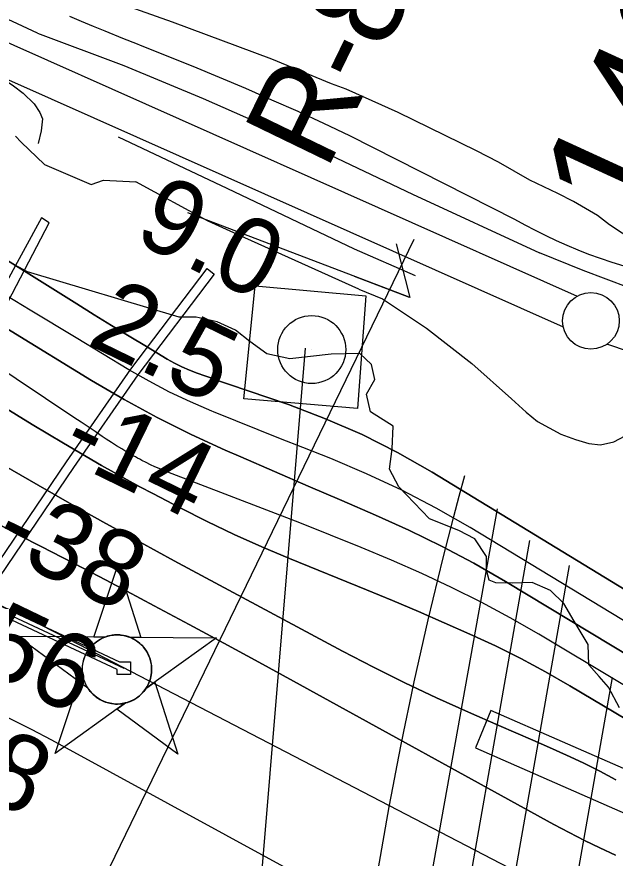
# Model space of a CAD drawing. Extents: x 3704301 to 3742427, y 506229 to 532009.
# Drawn here: x 3709180 to 3709708, y 522807 to 523550 of the extents above; entities that cross this region are included whole.
import ezdxf

# ---------------------------------------------------------------- set-up
doc = ezdxf.new("R2010")
doc.units = 0
for name, color, linetype in [('V-CHAN-DOCK', 7, 'Continuous'), ('V-CHAN-NAID', 7, 'Continuous'), ('V-DOMW-TANK', 7, 'Continuous'), ('V-FLOD-BASE', 7, 'Continuous'), ('V-LEVE-TOET', 7, 'Continuous'), ('V-RIVR-EDGE', 7, 'Continuous'), ('V-RIVR-RANG', 7, 'Continuous'), ('V-RIVR-RANG-IDEN', 7, 'Continuous'), ('V-ROAD-CNTR', 7, 'Continuous'), ('V-RRAP-FSHR', 7, 'Continuous'), ('V-SITE-OTLN', 7, 'Continuous'), ('V-SURV-IDEN', 7, 'Continuous'), ('V-SURV-LINE', 7, 'Continuous'), ('V-TOPO-DPTH', 7, 'Continuous'), ('V-TOPO-MAJR', 7, 'Continuous'), ('V-TOPO-MINR', 7, 'Continuous'), ('V-TOPO-WATR', 7, 'Continuous'), ('V-UTIL-LINE', 7, 'Continuous')]:
    doc.layers.add(name, color=color, linetype=linetype)

msp = doc.modelspace()

# ---------------------------------------------------------------- linework, layer by layer
at = {"layer": 'V-CHAN-DOCK'}
for points in [[(3709201.26, 523372.33), (3709132.68, 523246.8), (3708935.23, 523340.97), (3708913.04, 523298.3), (3709120.9, 523201.18), (3709208.21, 523367.89), (3709201.26, 523372.33)], [(3709143.74, 523039.46), (3709223.58, 523156.83), (3709280.37, 523238.73), (3709347.55, 523327.59), (3709353.71, 523322.56), (3709286.53, 523233.7), (3709229.73, 523151.8), (3709151, 523036.06), (3709270.29, 522980.22), (3709280.08, 522980.2), (3709280.05, 522969.09), (3709268.05, 522969.11), (3709268.06, 522973.54), (3709012.15, 523093.33), (3709002.64, 523093.35), (3709002.67, 523104.47), (3709014.67, 523104.44), (3709014.66, 523099.89), (3709143.74, 523039.46)], [(3709895.66, 522947.67), (3709851.16, 522826.73), (3709598.14, 522937.2), (3709584.47, 522904.42), (3710133.28, 522663.55), (3710146.76, 522694.23), (3709855.88, 522822.62), (3709900.97, 522945.91), (3709895.66, 522947.67)]]:
    msp.add_lwpolyline(points, dxfattribs=at)
msp.add_lwpolyline([(3709480.27, 523203.97), (3709380.15, 523212.56), (3709389.92, 523312.09), (3709487.68, 523303.49)], close=True, dxfattribs=at)
at = {"layer": 'V-CHAN-NAID'}
for points in [[(3709257.18, 523002.07), (3709247.59, 523002.14), (3709268.71, 523065.62), (3709288.94, 523001.84), (3709279.35, 523001.91), (3709277.77, 523002.49), (3709275.68, 523003.11), (3709273.64, 523003.56), (3709271.6, 523003.87), (3709270.44, 523003.98), (3709268.9, 523004.06), (3709267.18, 523004.06), (3709265.81, 523003.99), (3709263.91, 523003.79), (3709262.54, 523003.57), (3709260.75, 523003.19), (3709259.23, 523002.77), (3709258.19, 523002.44)], [(3709257.18, 523002.07), (3709180.69, 523002.61), (3709242.25, 522957.21), (3709241.14, 522959.12), (3709240.33, 522960.75), (3709239.5, 522962.72), (3709238.81, 522964.77), (3709238.44, 522966.09), (3709238.08, 522967.72), (3709237.84, 522969.17), (3709237.65, 522970.76), (3709237.54, 522972.5), (3709237.53, 522974.08), (3709237.63, 522976.15), (3709237.82, 522977.77), (3709238.21, 522979.98), (3709238.69, 522981.9), (3709239.29, 522983.79), (3709239.95, 522985.46), (3709240.68, 522987.05), (3709241.49, 522988.59), (3709242.55, 522990.32), (3709243.58, 522991.79), (3709244.58, 522993.06), (3709245.58, 522994.21), (3709246.89, 522995.55), (3709247.94, 522996.51), (3709249.66, 522997.91), (3709250.87, 522998.78), (3709252.56, 522999.85), (3709254.29, 523000.79), (3709255.74, 523001.48)], [(3709279.35, 523001.91), (3709355.84, 523001.37), (3709293.64, 522956.85), (3709294.55, 522958.34), (3709295.53, 522960.18), (3709296.25, 522961.77), (3709296.98, 522963.72), (3709297.53, 522965.51), (3709297.93, 522967.15), (3709298.29, 522969.16), (3709298.47, 522970.73), (3709298.6, 522972.94), (3709298.57, 522975), (3709298.38, 522977.22), (3709298.11, 522978.98), (3709297.62, 522981.21), (3709296.98, 522983.35), (3709296.23, 522985.33), (3709295.58, 522986.77), (3709294.58, 522988.69), (3709293.52, 522990.41), (3709292.3, 522992.11), (3709291.04, 522993.65), (3709289.77, 522995.02), (3709288.14, 522996.55), (3709286.39, 522997.96), (3709284.71, 522999.14), (3709282.82, 523000.27), (3709281.35, 523001.03)], [(3709275.61, 522943.94), (3709213.41, 522899.42), (3709234.53, 522962.9), (3709242.25, 522957.21), (3709242.89, 522956.25), (3709244.27, 522954.39), (3709245.48, 522952.97), (3709246.95, 522951.47), (3709248.34, 522950.22), (3709249.79, 522949.06), (3709251.19, 522948.08), (3709252.87, 522947.04), (3709254.58, 522946.13), (3709256.38, 522945.32), (3709257.82, 522944.76), (3709259.45, 522944.23), (3709261.68, 522943.67), (3709263.21, 522943.38), (3709265.23, 522943.12), (3709266.77, 522943.02), (3709268.63, 522943), (3709270.32, 522943.08), (3709272.03, 522943.25), (3709273.93, 522943.56)], [(3709293.64, 522956.85), (3709301.44, 522962.43), (3709321.66, 522898.65), (3709267.81, 522938.36), (3709275.61, 522943.94), (3709277.28, 522944.42), (3709278.89, 522944.98), (3709281.05, 522945.89), (3709282.78, 522946.78), (3709284.65, 522947.89), (3709286.39, 522949.1), (3709287.94, 522950.35), (3709289.23, 522951.51), (3709290.61, 522952.93), (3709291.81, 522954.34), (3709292.93, 522955.81)]]:
    msp.add_lwpolyline(points, close=True, dxfattribs=at)
msp.add_circle((3709268.06, 522973.53), 30.54, dxfattribs=at)
at = {"layer": 'V-DOMW-TANK'}
msp.add_line((3709439.97, 523255.98), (3709439.97, 523255.98), dxfattribs=at)
msp.add_circle((3709439.97, 523255.98), 30, dxfattribs=at)
at = {"layer": 'V-FLOD-BASE'}
for points in [[(3708672.81, 523755.58), (3708745.33, 523708.9), (3708803.64, 523671.65), (3708829.23, 523656.1), (3708842.97, 523649.03), (3708909.77, 523618.9), (3708991.73, 523582.65), (3709081.74, 523545.01), (3709117.28, 523527.58), (3709134.82, 523516.74), (3709176.53, 523488.92), (3709185.06, 523482.31), (3709195.03, 523472.87), (3709199.78, 523465.31), (3709202.16, 523459.63), (3709201.23, 523449.22), (3709198.42, 523437.86)], [(3709268.93, 523443.71), (3709365.1, 523398.5), (3709477.4, 523344.82), (3709531.41, 523321.28)]]:
    msp.add_lwpolyline(points, dxfattribs=at)
at = {"layer": 'V-LEVE-TOET'}
for points in [[(3709197.72, 523535.35), (3709110.54, 523576.31), (3709007.73, 523622.45), (3708906.81, 523670.48), (3708855.63, 523696.86), (3708767.94, 523754.86), (3708757.73, 523761.46)], [(3709197.72, 523535.35), (3709274.16, 523506.81), (3709344.24, 523477.55), (3709443.56, 523433.73), (3709528.93, 523393.12), (3709641.15, 523341.42)], [(3709178.5, 523444.5), (3709183.37, 523439.05), (3709203.89, 523419.31), (3709245.21, 523401.81), (3709256.13, 523405.48), (3709284.61, 523404.06)], [(3709481.71, 523309.4), (3709380.8, 523354.59), (3709348.58, 523369.19), (3709284.61, 523404.06)], [(3709720.26, 523310.38), (3709679.52, 523325.9), (3709641.15, 523341.42)], [(3709481.71, 523309.4), (3709502.36, 523300.61), (3709541.33, 523274.77), (3709581.48, 523243.62), (3709616.33, 523212.47), (3709629.33, 523200.71), (3709639.36, 523192.48), (3709660.02, 523181.34), (3709673, 523176.65), (3709684.79, 523173.14), (3709694.82, 523171.99), (3709706.6, 523174.37), (3709716.61, 523179.7), (3709724.84, 523187.97), (3709733.64, 523203.32), (3709740.09, 523216.89), (3709745.97, 523222.8), (3709748.33, 523222.8), (3709754.05, 523222.02)]]:
    msp.add_lwpolyline(points, dxfattribs=at)
at = {"layer": 'V-RIVR-EDGE'}
for points in [[(3709569.74, 523096.19), (3709543.96, 523106.46), (3709517.01, 523134.74), (3709508.64, 523150.37), (3709511.09, 523168.38), (3709511.74, 523188.19), (3709491.96, 523200.84), (3709488.4, 523216.46), (3709495.63, 523229.65), (3709492.66, 523242.86), (3709482.48, 523252.49), (3709457.27, 523251.96), (3709420.64, 523247.84), (3709400.24, 523252.1), (3709385.26, 523262.94), (3709372.67, 523273.18), (3709356.48, 523280.42), (3709337.88, 523284.67), (3709322.88, 523284.7), (3709189.1, 523324.66), (3709153.73, 523343.35)], [(3709711.63, 522939.76), (3709702.07, 522957.79), (3709693.69, 522967.42), (3709684.71, 522977.64), (3709684.16, 522995.65), (3709671.6, 523016.1), (3709662.64, 523031.73), (3709650.66, 523043.16), (3709634.47, 523050.41), (3709617.06, 523049.85), (3709602.65, 523049.89), (3709596.65, 523052.3), (3709594.27, 523061.31), (3709594.3, 523073.32), (3709584.13, 523088.95), (3709569.74, 523096.19)]]:
    msp.add_lwpolyline(points, dxfattribs=at)
at = {"layer": 'V-RIVR-RANG'}
msp.add_line((3709530.16, 523353.05), (3709198.71, 522669.13), dxfattribs=at)
at = {"layer": 'V-ROAD-CNTR'}
msp.add_lwpolyline([(3709715.77, 523329.67), (3709705.35, 523332.86), (3709695, 523336.25), (3709684.72, 523339.84), (3709675.13, 523343.66), (3709665.61, 523347.7), (3709656.18, 523351.93), (3709646.83, 523356.37), (3709637.59, 523361.02), (3709628.44, 523365.85), (3709619.39, 523370.89), (3709473.57, 523444.78), (3709450.77, 523455.5), (3709427.87, 523466.01), (3709404.87, 523476.3), (3709381.79, 523486.39), (3709358.61, 523496.27), (3709335.34, 523505.93), (3709319.79, 523512.08), (3709304.25, 523518.26), (3709288.72, 523524.47), (3709286.08, 523525.53), (3709273.21, 523530.7), (3709257.71, 523536.95), (3709247.24, 523541.16), (3709236.84, 523545.56), (3709226.52, 523550.15)], dxfattribs=at)
at = {"layer": 'V-RRAP-FSHR'}
msp.add_line((3709526.89, 523301.86), (3709514.96, 523349.21), dxfattribs=at)
for points in [[(3709526.14, 523302.14), (3709330.65, 523376.62)], [(3709477.56, 523320.65), (3709526.14, 523302.14)]]:
    msp.add_lwpolyline(points, dxfattribs=at)
at = {"layer": 'V-SITE-OTLN'}
for p, q in [((3709316.96, 523545.05), (3709211.96, 523582.52)), ((3709404.86, 523512.25), (3709316.96, 523545.05)), ((3709457.37, 523490.57), (3709404.86, 523512.25)), ((3709470.35, 523485.88), (3709457.37, 523490.57)), ((3709516.37, 523465.36), (3709470.35, 523485.88)), ((3709585.41, 523431.34), (3709516.37, 523465.36)), ((3709604.89, 523421.37), (3709585.41, 523431.34)), ((3709632.62, 523405.52), (3709604.89, 523421.37)), ((3709657.41, 523393.79), (3709632.62, 523405.52)), ((3709670.98, 523386.75), (3709657.41, 523393.79)), ((3709692.23, 523374.43), (3709670.98, 523386.75)), ((3709702.86, 523366.2), (3709692.23, 523374.43)), ((3709740.64, 523340.95), (3709702.86, 523366.2))]:
    msp.add_line(p, q, dxfattribs=at)
at = {"layer": 'V-SURV-LINE'}
for points in [[(3709146.91, 523538.08), (3709674.37, 523303.1)], [(3709662.17, 523275.69), (3709134.71, 523510.67)], [(3709819.76, 523220.4), (3709700.65, 523260.66)]]:
    msp.add_lwpolyline(points, dxfattribs=at)
msp.add_circle((3709686.52, 523281.27), 25, dxfattribs=at)
at = {"layer": 'V-TOPO-DPTH'}
for points in [[(3708812.76, 523491.81), (3708918.01, 523428.33), (3708982.24, 523389.49), (3709046.42, 523350.55), (3709110.51, 523311.48), (3709174.54, 523272.31), (3709245.62, 523228.72), (3709274.39, 523211.89), (3709303.58, 523195.88), (3709333.42, 523181.1), (3709363.68, 523167.13), (3709377.41, 523161.13), (3709407.05, 523148.23), (3709436.72, 523135.38), (3709466.42, 523122.61), (3709496.15, 523109.89), (3709525.58, 523096.6), (3709554.6, 523082.51), (3709583, 523067.22), (3709611, 523051.13), (3710304.55, 522633)], [(3710304.55, 522633), (3709611, 523051.13), (3709583, 523067.22), (3709554.6, 523082.51), (3709525.58, 523096.6), (3709496.15, 523109.89), (3709466.42, 523122.61), (3709436.72, 523135.38), (3709407.05, 523148.23), (3709377.41, 523161.13), (3709363.68, 523167.13), (3709333.42, 523181.1), (3709303.58, 523195.88), (3709274.39, 523211.89), (3709245.62, 523228.72), (3709174.54, 523272.31), (3709110.51, 523311.48), (3709046.42, 523350.55), (3708982.24, 523389.49), (3708918.01, 523428.33), (3708812.76, 523491.81)], [(3709708.23, 522809.65), (3709694.45, 522816.02), (3709680.78, 522822.63), (3709667.27, 522829.56), (3709653.88, 522836.72), (3709423.97, 522963.19), (3709393.25, 522980), (3709362.49, 522996.72), (3709331.66, 523013.3), (3709300.78, 523029.8), (3709276.59, 523042.65), (3709257.75, 523052.61), (3709238.87, 523062.53), (3709219.96, 523072.36), (3709201.02, 523082.14), (3709182.08, 523091.93), (3709163.17, 523101.79), (3709144.32, 523111.73), (3709125.49, 523121.74), (3708672.25, 523364.16)], [(3708672.25, 523364.16), (3709125.49, 523121.74), (3709144.32, 523111.73), (3709163.17, 523101.79), (3709182.08, 523091.93), (3709201.02, 523082.14), (3709219.96, 523072.36), (3709238.87, 523062.53), (3709257.75, 523052.61), (3709276.59, 523042.65), (3709300.78, 523029.8), (3709331.66, 523013.3), (3709362.49, 522996.72), (3709393.25, 522980), (3709423.97, 522963.19), (3709653.88, 522836.72), (3709667.27, 522829.56), (3709680.78, 522822.63), (3709694.45, 522816.02), (3709708.23, 522809.65)], [(3709171.28, 523334.63), (3709201.92, 523315.44), (3709232.7, 523296.21), (3709247.99, 523286.71), (3709263.31, 523277.27), (3709278.67, 523267.9), (3709294.07, 523258.59), (3709312.35, 523247.59), (3709318.73, 523244.01), (3709325.23, 523240.7), (3709331.92, 523237.79), (3709338.73, 523235.15), (3709345.64, 523232.72), (3709352.56, 523230.3), (3709359.48, 523227.9), (3709366.41, 523225.51), (3709419.33, 523207.36), (3709452.23, 523194.87), (3709484.48, 523180.99), (3709515.76, 523165.04), (3709546.39, 523147.71), (3710477.48, 522580.05)], [(3709708.54, 522876.08), (3709694.22, 522883.78), (3709679.64, 522890.99), (3709664.89, 522897.87), (3709650, 522904.47), (3709635.09, 522911.05), (3709620.17, 522917.59), (3709605.24, 522924.11), (3709578.34, 522935.81), (3709550.12, 522948.5), (3709522.12, 522961.65), (3709494.46, 522975.49), (3709467.02, 522989.79), (3709318.6, 523069.49), (3709288.39, 523085.89), (3709258.26, 523102.46), (3709228.29, 523119.3), (3709198.41, 523136.32), (3709079.86, 523204.51), (3709015.88, 523242.2), (3708952.45, 523280.76), (3708889.83, 523320.62)], [(3708889.83, 523320.62), (3708952.45, 523280.76), (3709015.88, 523242.2), (3709079.86, 523204.51), (3709198.41, 523136.32), (3709228.29, 523119.3), (3709258.26, 523102.46), (3709288.39, 523085.89), (3709318.6, 523069.49), (3709467.02, 522989.79), (3709494.46, 522975.49), (3709522.12, 522961.65), (3709550.12, 522948.5), (3709578.34, 522935.81), (3709605.24, 522924.11), (3709620.17, 522917.59), (3709635.09, 522911.05), (3709650, 522904.47), (3709664.89, 522897.87), (3709679.64, 522890.99), (3709694.22, 522883.78), (3709708.54, 522876.08)], [(3710126.1, 522686.83), (3709667.89, 522959.16), (3709646.31, 522971.47), (3709624.47, 522983.27), (3709602.22, 522994.29), (3709579.71, 523004.79), (3709556.95, 523014.79), (3709534.13, 523024.65), (3709511.21, 523034.29), (3709488.24, 523043.79), (3709420.3, 523071.5), (3709395.84, 523081.87), (3709371.59, 523092.7), (3709347.65, 523104.19), (3709323.92, 523116.14), (3709299.63, 523128.79), (3709288.24, 523134.83), (3709276.91, 523140.97), (3709265.66, 523147.27), (3709254.48, 523153.68), (3709220.84, 523173.26), (3709193.07, 523189.83), (3709165.55, 523206.81)], [(3709165.55, 523206.81), (3709193.07, 523189.83), (3709220.84, 523173.26), (3709254.48, 523153.68), (3709265.66, 523147.27), (3709276.91, 523140.97), (3709288.24, 523134.83), (3709299.63, 523128.79), (3709323.92, 523116.14), (3709347.65, 523104.19), (3709371.59, 523092.7), (3709395.84, 523081.87), (3709420.3, 523071.5), (3709488.24, 523043.79), (3709511.21, 523034.29), (3709534.13, 523024.65), (3709556.95, 523014.79), (3709579.71, 523004.79), (3709602.22, 522994.29), (3709624.47, 522983.27), (3709646.31, 522971.47), (3709667.89, 522959.16), (3710126.1, 522686.83)]]:
    msp.add_lwpolyline(points, dxfattribs=at)
at = {"layer": 'V-TOPO-MAJR'}
msp.add_lwpolyline([(3709709.54, 522748.21), (3709681.1, 522763.44), (3709652.55, 522778.47), (3709234.96, 522995.27), (3709223.48, 523001.17), (3709211.97, 523007.02), (3709200.42, 523012.78), (3709188.83, 523018.48), (3708709.33, 523252.26), (3708695.64, 523258.99), (3708681.97, 523265.77), (3708668.35, 523272.64), (3708654.76, 523279.57), (3708641.25, 523286.64), (3708627.81, 523293.85), (3708614.48, 523301.25), (3708601.22, 523308.8), (3708431.37, 523407.12)], dxfattribs=at)
at = {"layer": 'V-TOPO-MINR'}
for points in [[(3710391.59, 522606.43), (3709579.82, 523098.74), (3709549.95, 523115.82), (3709519.57, 523131.86), (3709488.41, 523146.34), (3709456.73, 523159.77), (3709432.16, 523169.45), (3709412.38, 523177.27), (3709392.62, 523185.13), (3709372.88, 523193.04), (3709353.15, 523200.99), (3709351.79, 523201.54), (3709332.97, 523209.67), (3709314.44, 523218.39), (3709296.35, 523227.98), (3709278.55, 523238.16), (3709232.09, 523266.2), (3709191.26, 523290.8), (3709150.4, 523315.34), (3709109.49, 523339.81), (3709068.55, 523364.23), (3708769.51, 523542.19)], [(3710304.55, 522633), (3709611, 523051.13), (3709583, 523067.22), (3709554.6, 523082.51), (3709525.58, 523096.6), (3709496.15, 523109.89), (3709466.42, 523122.61), (3709436.72, 523135.38), (3709407.05, 523148.23), (3709377.41, 523161.13), (3709363.68, 523167.13), (3709333.42, 523181.1), (3709303.58, 523195.88), (3709274.39, 523211.89), (3709245.62, 523228.72), (3709174.54, 523272.31), (3709110.51, 523311.48), (3709046.42, 523350.55), (3708982.24, 523389.49), (3708918.01, 523428.33), (3708812.76, 523491.81)], [(3709708.23, 522809.65), (3709694.45, 522816.02), (3709680.78, 522822.63), (3709667.27, 522829.56), (3709653.88, 522836.72), (3709423.97, 522963.19), (3709393.25, 522980), (3709362.49, 522996.72), (3709331.66, 523013.3), (3709300.78, 523029.8), (3709276.59, 523042.65), (3709257.75, 523052.61), (3709238.87, 523062.53), (3709219.96, 523072.36), (3709201.02, 523082.14), (3709182.08, 523091.93), (3709163.17, 523101.79), (3709144.32, 523111.73), (3709125.49, 523121.74), (3708672.25, 523364.16)], [(3709708.54, 522876.08), (3709694.22, 522883.78), (3709679.64, 522890.99), (3709664.89, 522897.87), (3709650, 522904.47), (3709635.09, 522911.05), (3709620.17, 522917.59), (3709605.24, 522924.11), (3709578.34, 522935.81), (3709550.12, 522948.5), (3709522.12, 522961.65), (3709494.46, 522975.49), (3709467.02, 522989.79), (3709318.6, 523069.49), (3709288.39, 523085.89), (3709258.26, 523102.46), (3709228.29, 523119.3), (3709198.41, 523136.32), (3709079.86, 523204.51), (3709015.88, 523242.2), (3708952.45, 523280.76), (3708889.83, 523320.62)], [(3710216.16, 522659.78), (3709640.39, 523004.59), (3709615.14, 523019.1), (3709589.57, 523032.98), (3709563.51, 523045.93), (3709537.12, 523058.25), (3709510.41, 523069.9), (3709483.58, 523081.27), (3709456.58, 523092.23), (3709429.47, 523102.92), (3709309.23, 523149.28), (3709305.29, 523150.87), (3709301.38, 523152.54), (3709297.53, 523154.33), (3709293.71, 523156.19), (3709289.97, 523158.09), (3709288.06, 523159.08), (3709286.16, 523160.1), (3709284.29, 523161.14), (3709282.42, 523162.2), (3709276.81, 523165.47), (3709272.18, 523168.23), (3709267.58, 523171.04), (3709263.04, 523173.95), (3709258.54, 523176.91), (3709255.01, 523179.29), (3709248.76, 523183.48), (3709242.51, 523187.68), (3709236.27, 523191.87), (3709230.01, 523196.05), (3709051.97, 523315.21)], [(3709725.98, 522628.79), (3709707.83, 522639.16), (3709689.6, 522649.37), (3709671.3, 522659.46), (3709210.48, 522911.01), (3709192.55, 522920.47), (3709174.44, 522929.59), (3709156.09, 522938.18), (3709137.56, 522946.43), (3708747.05, 523113.65), (3708718, 523125.84), (3708688.83, 523137.75), (3708659.5, 523149.23), (3708630.05, 523160.44), (3708585.72, 523176.94), (3708578.39, 523179.76), (3708571.11, 523182.7), (3708563.89, 523185.81), (3708556.72, 523189.02), (3708466.78, 523230.6), (3708433.26, 523246.51)], [(3710126.1, 522686.83), (3709667.89, 522959.16), (3709646.31, 522971.47), (3709624.47, 522983.27), (3709602.22, 522994.29), (3709579.71, 523004.79), (3709556.95, 523014.79), (3709534.13, 523024.65), (3709511.21, 523034.29), (3709488.24, 523043.79), (3709420.3, 523071.5), (3709395.84, 523081.87), (3709371.59, 523092.7), (3709347.65, 523104.19), (3709323.92, 523116.14), (3709299.63, 523128.79), (3709288.24, 523134.83), (3709276.91, 523140.97), (3709265.66, 523147.27), (3709254.48, 523153.68), (3709220.84, 523173.26), (3709193.07, 523189.83), (3709165.55, 523206.81)]]:
    msp.add_lwpolyline(points, dxfattribs=at)
at = {"layer": 'V-TOPO-WATR'}
msp.add_lwpolyline([(3710477.48, 522580.05), (3709546.39, 523147.71), (3709515.76, 523165.04), (3709484.48, 523180.99), (3709452.23, 523194.87), (3709419.33, 523207.36), (3709366.41, 523225.51), (3709359.48, 523227.9), (3709352.56, 523230.3), (3709345.64, 523232.72), (3709338.73, 523235.15), (3709331.92, 523237.79), (3709325.23, 523240.7), (3709318.73, 523244.01), (3709312.35, 523247.59), (3709294.07, 523258.59), (3709278.67, 523267.9), (3709263.31, 523277.27), (3709247.99, 523286.71), (3709232.7, 523296.21), (3709201.92, 523315.44), (3709171.28, 523334.63)], dxfattribs=at)
at = {"layer": 'V-UTIL-LINE'}
for p, q in [((3709183.71, 520238.44), (3709434.58, 523257.06)), ((3709144.84, 520560.43), (3709604.06, 523115.23)), ((3709008.66, 523098.83), (3709274.06, 522974.59)), ((3709187.31, 520557.79), (3709632.43, 523087.48)), ((3709222.56, 520535.75), (3709667.68, 523065.44)), ((3709276.24, 520520.33), (3709705.48, 522966.28))]:
    msp.add_line(p, q, dxfattribs=at)
msp.add_lwpolyline([(3709498.7, 522796.65), (3709501.82, 522815.15), (3709505.05, 522833.64), (3709508.38, 522852.11), (3709511.81, 522870.56), (3709515.34, 522888.99), (3709518.97, 522907.4), (3709522.7, 522925.79), (3709526.52, 522944.17), (3709530.45, 522962.52), (3709534.47, 522980.85), (3709538.6, 522999.16), (3709542.82, 523017.44), (3709547.14, 523035.71), (3709551.56, 523053.95), (3709556.08, 523072.16), (3709560.69, 523090.35), (3709565.41, 523108.52), (3709570.22, 523126.66), (3709575.13, 523144.77)], dxfattribs=at)

# ---------------------------------------------------------------- texts
at = {"layer": 'V-RIVR-RANG'}
for s, rotation, p in [('9.0', 333.99833, (3709281.13, 523352.51)), ('9.0', 333.99833, (3709281.13, 523352.51)), ('2.5', 333.99833, (3709240.12, 523261.25)), ('2.5', 333.99833, (3709240.12, 523261.25)), ('-14', 333.99833, (3709215.48, 523162.01)), ('-14', 333.99833, (3709215.48, 523162.01)), ('-38', 333.99833, (3709155.5, 523080)), ('-56', 334.28336, (3709113.76, 522988.66)), ('-68', 334.28336, (3709071.57, 522897.98))]:
    msp.add_text(s, height=67, rotation=rotation, dxfattribs=at).set_placement(p)
at = {"layer": 'V-RIVR-RANG-IDEN'}
msp.add_text('R-89.3', height=83, rotation=64.14168, dxfattribs=at).set_placement((3709452.87, 523412.62))
at = {"layer": 'V-SURV-IDEN'}
msp.add_text('140+76.3', height=100, rotation=65.35725, dxfattribs=at).set_placement((3709729.77, 523359.91))

doc.saveas('drawing.dxf')
